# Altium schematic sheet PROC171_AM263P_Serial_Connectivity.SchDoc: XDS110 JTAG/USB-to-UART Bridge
size 431 x 279 mm; Date: Not shown in title block; ApprovedBy: Not shown in title block; CheckedBy: Not shown in title block; Author: Not shown in title block; CompanyName: Not shown in title block; Engineer: Not shown in title block; Organization: Not shown in title block; Address1: Not shown in title block; Address2: Not shown in title block; Address3: Not shown in title block; Address4: Not shown in title block; DocumentNumber: 6; Revision: Use project parameter SCH_Rev; SheetNumber: 6; SheetTotal: 26; PageSetup: Record=PageOptions¦CenterHorizontal=True¦CenterVertical=True¦PrintScale=1.00¦XCorrection=1.00¦YCorrection=1.00¦PrintKind=0¦BorderSize=5000000¦LeftOffset=0¦BottomOffset=0¦Orientation=2¦PaperLength=1000¦PaperWidth=1000¦Scale=100¦PaperSource=15¦PrintQuality=600¦MediaType=1¦DitherType=10¦PaperKind=Letter¦PrintScaleMode=1
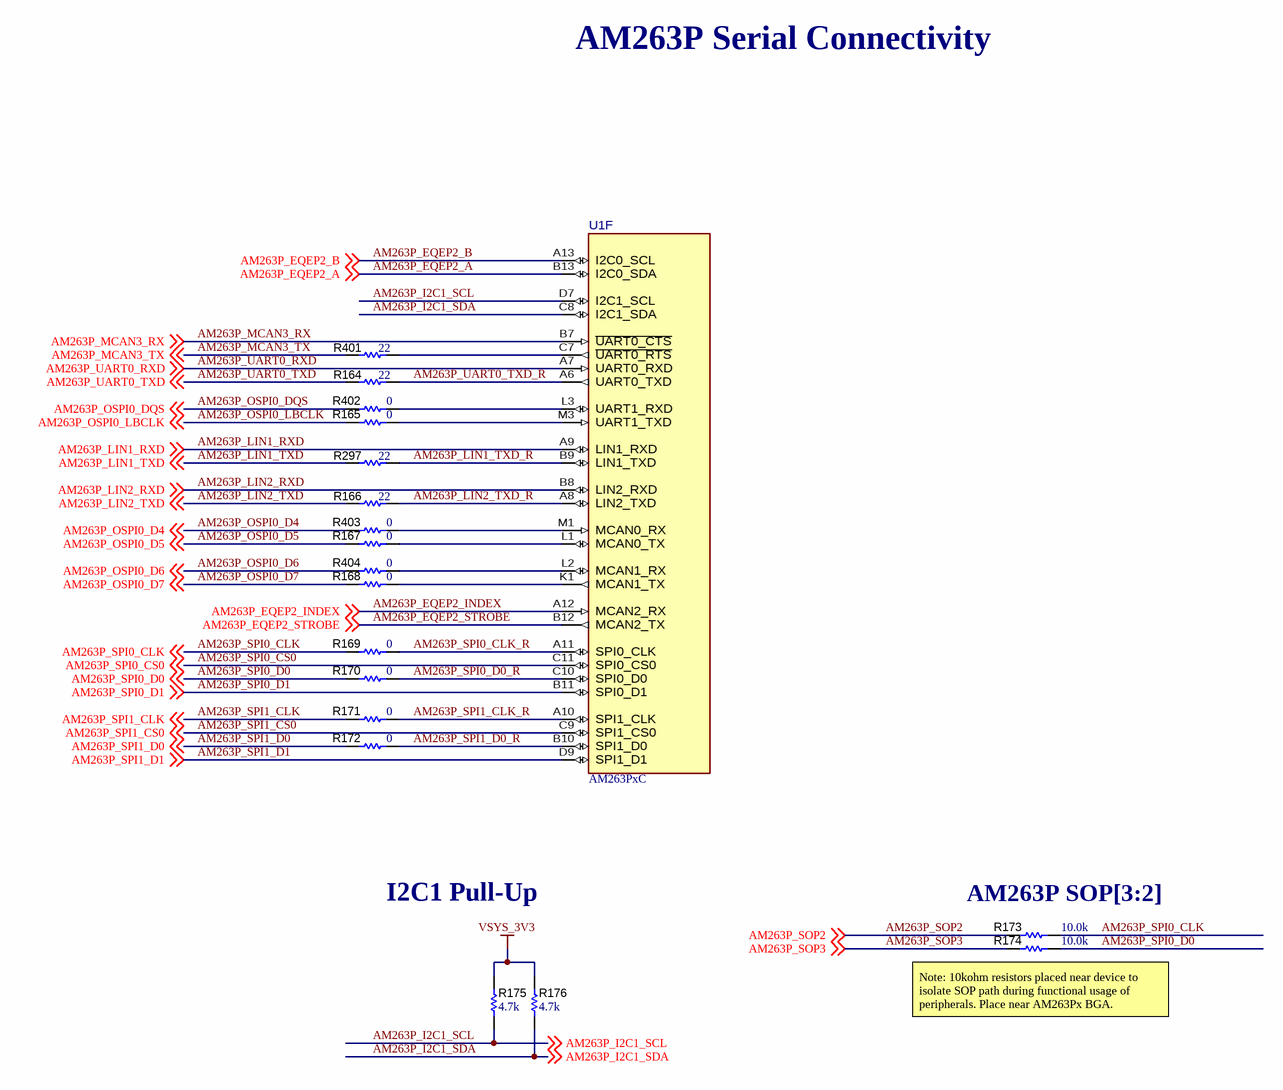
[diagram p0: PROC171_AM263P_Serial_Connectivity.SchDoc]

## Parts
R164  ValueDisplayed: 22  [0402]  (hidden comment: CRCW040222R0JNED)
R165  value 0  [0402L]  (hidden comment: ERJ-2GE0R00X)
R166  ValueDisplayed: 22  [0402]  (hidden comment: CRCW040222R0JNED)
R167  value 0  [0402L]  (hidden comment: ERJ-2GE0R00X)
R168  value 0  [0402L]  (hidden comment: ERJ-2GE0R00X)
R169  value 0  [0402L]  (hidden comment: ERJ-2GE0R00X)
R170  value 0  [0402L]  (hidden comment: ERJ-2GE0R00X)
R171  value 0  [0402L]  (hidden comment: ERJ-2GE0R00X)
R172  value 0  [0402L]  (hidden comment: ERJ-2GE0R00X)
R173  ValueDisplayed: 10.0k  [0402]  (hidden comment: ERJ-2RKF1002X)
R174  ValueDisplayed: 10.0k  [0402]  (hidden comment: ERJ-2RKF1002X)
R175  ValueDisplayed: 4.7k  [0402]  (hidden comment: CRCW04024K70JNED)
R176  ValueDisplayed: 4.7k  [0402]  (hidden comment: CRCW04024K70JNED)
R297  ValueDisplayed: 22  [0402]  (hidden comment: CRCW040222R0JNED)
R401  ValueDisplayed: 22  [0402]  (hidden comment: CRCW040222R0JNED)
R402  value 0  [0402L]  (hidden comment: ERJ-2GE0R00X)
R403  value 0  [0402L]  (hidden comment: ERJ-2GE0R00X)
R404  value 0  [0402L]  (hidden comment: ERJ-2GE0R00X)
U1  AM263PxC  [ZCZ0324A-MFG]  (part F of 13)

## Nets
VSYS_3V3: R175.2 R176.2
AM263P_EQEP2_A: U1.B13(I2C0_SDA) ; off-sheet AM263P_EQEP2_A
AM263P_EQEP2_B: U1.A13(I2C0_SCL) ; off-sheet AM263P_EQEP2_B
AM263P_EQEP2_INDEX: U1.A12(MCAN2_RX) ; off-sheet AM263P_EQEP2_INDEX
AM263P_EQEP2_STROBE: U1.B12(MCAN2_TX) ; off-sheet AM263P_EQEP2_STROBE
AM263P_I2C1_SCL: R175.1 U1.D7(I2C1_SCL) ; off-sheet AM263P_I2C1_SCL
AM263P_I2C1_SDA: R176.1 U1.C8(I2C1_SDA) ; off-sheet AM263P_I2C1_SDA
AM263P_LIN1_RXD: U1.A9(LIN1_RXD) ; off-sheet AM263P_LIN1_RXD
AM263P_LIN1_TXD: R297.1 ; off-sheet AM263P_LIN1_TXD
AM263P_LIN1_TXD_R: R297.2 U1.B9(LIN1_TXD)
AM263P_LIN2_RXD: U1.B8(LIN2_RXD) ; off-sheet AM263P_LIN2_RXD
AM263P_LIN2_TXD: R166.1 ; off-sheet AM263P_LIN2_TXD
AM263P_LIN2_TXD_R: R166.2 U1.A8(LIN2_TXD)
AM263P_MCAN3_RX: U1.B7(~{UART0_CTS}) ; off-sheet AM263P_MCAN3_RX
AM263P_MCAN3_TX: R401.1 ; off-sheet AM263P_MCAN3_TX
AM263P_OSPI0_D4: R403.1 ; off-sheet AM263P_OSPI0_D4
AM263P_OSPI0_D5: R167.1 ; off-sheet AM263P_OSPI0_D5
AM263P_OSPI0_D6: R404.1 ; off-sheet AM263P_OSPI0_D6
AM263P_OSPI0_D7: R168.1 ; off-sheet AM263P_OSPI0_D7
AM263P_OSPI0_DQS: R402.1 ; off-sheet AM263P_OSPI0_DQS
AM263P_OSPI0_LBCLK: R165.1 ; off-sheet AM263P_OSPI0_LBCLK
AM263P_SOP2: R173.2 ; off-sheet AM263P_SOP2
AM263P_SOP3: R174.2 ; off-sheet AM263P_SOP3
AM263P_SPI0_CLK: R169.1 R173.1 ; off-sheet AM263P_SPI0_CLK
AM263P_SPI0_CLK_R: R169.2 U1.A11(SPI0_CLK)
AM263P_SPI0_CS0: U1.C11(SPI0_CS0) ; off-sheet AM263P_SPI0_CS0
AM263P_SPI0_D0: R170.1 R174.1 ; off-sheet AM263P_SPI0_D0
AM263P_SPI0_D0_R: R170.2 U1.C10(SPI0_D0)
AM263P_SPI0_D1: U1.B11(SPI0_D1) ; off-sheet AM263P_SPI0_D1
AM263P_SPI1_CLK: R171.1 ; off-sheet AM263P_SPI1_CLK
AM263P_SPI1_CLK_R: R171.2 U1.A10(SPI1_CLK)
AM263P_SPI1_CS0: U1.C9(SPI1_CS0) ; off-sheet AM263P_SPI1_CS0
AM263P_SPI1_D0: R172.1 ; off-sheet AM263P_SPI1_D0
AM263P_SPI1_D0_R: R172.2 U1.B10(SPI1_D0)
AM263P_SPI1_D1: U1.D9(SPI1_D1) ; off-sheet AM263P_SPI1_D1
AM263P_UART0_RXD: U1.A7(UART0_RXD) ; off-sheet AM263P_UART0_RXD
AM263P_UART0_TXD: R164.1 ; off-sheet AM263P_UART0_TXD
AM263P_UART0_TXD_R: R164.2 U1.A6(UART0_TXD)
NetR165_2: R165.2 U1.M3(UART1_TXD)
NetR167_2: R167.2 U1.L1(MCAN0_TX)
NetR168_2: R168.2 U1.K1(MCAN1_TX)
NetR401_2: R401.2 U1.C7(~{UART0_RTS})
NetR402_2: R402.2 U1.L3(UART1_RXD)
NetR403_2: R403.2 U1.M1(MCAN0_RX)
NetR404_2: R404.2 U1.L2(MCAN1_RX)

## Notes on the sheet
- AM263P Serial Connectivity
- I2C1 Pull-Up
- AM263P SOP[3:2]
- (near R174) Note: 10kohm resistors placed near device to isolate SOP path during functional usage of peripherals. Place near AM263Px BGA.

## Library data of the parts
R164 R166 R297 R401 = CMP-0026880-3: RES, 22, 5%, 0.063 W, AEC-Q200 Grade 0, 0402; Manufacturer: Vishay-Dale; Power_W: 63mW; TempCo: 200 ppm/C; Value_Code: 22R0; Value: 22; EIA_Code: E24; SizeX_mm: 1; SizeY_mm: 0.5; SizeZ_mm: 0.6; Value2: 0.063W; AEC Qualified: Y; VDC_V: 50V; AEC Category: Q200; AEC Grade: 0
R165 R167-R172 R402-R404 = CMP-0026992-3: RES, 0, 5%, 0.1 W, AEC-Q200 Grade 0, 0402; Manufacturer: Panasonic; Power_W: 100mW; TempCo: 600 ppm/C; Value_Code: 0000; EIA_Code: E24; SizeX_mm: 1; SizeY_mm: 0.5; SizeZ_mm: 0.6; Value2: 0.1W; AEC Qualified: Y; VDC_V: 50V; AEC Category: Q200; SizeAreaWB_mm2: 3
R173 R174 = CMP-0026658-1: RES, 10.0 k, 1%, 0.1 W, 0402; Manufacturer: Panasonic; Power_W: 100mW; TempCo: 100 ppm/C; Value_Code: 10k0; U/M: EA; Value: 10.0k; EIA_Code: E96; Res_ohm: 10k; SizeX_mm: 1; SizeY_mm: 0.5; SizeZ_mm: 0.6; Value2: 0.1W; VDC_V: 50V; AEC Category: Q200
R175 R176 = CMP-0026938-5: RES, 4.7 k, 5%, 0.063 W, AEC-Q200 Grade 0, 0402; Manufacturer: Vishay-Dale; Power_W: 63mW; TempCo: 200 ppm/C; Value_Code: 4k70; Value: 4.7k; EIA_Code: E24; SizeX_mm: 1; SizeY_mm: 0.5; SizeZ_mm: 0.6; Value2: 0.063W; AEC Qualified: Y; VDC_V: 50V; AEC Category: Q200; AEC Grade: 0
U1 = CMP-0001698-2: Sitara™ Microcontroller; Manufacturer: Texas Instruments; SizeZ_mm: 1.4mm; Core Architecture: ARM Cortex-R5F; Data Bus Width: 32bits; Frequency_Fixed: 200MHz; Interface: I2C,SPI,UART,CAN,LIN,Ethernet,Other; Max Supply Voltage: 3.465V; Memory Size: 2MBytes; Memory Type: RAM; Min Supply Voltage: 1.14V; Number Of Cores: 1; Number Of I/Os: 140; Number Of I2C Channels: 4; Number Of Spi Channels: 5; Number Of Uart Channels: 6; Standoff Height: 0.35mm; AEC Category: Q200; CompType: IC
